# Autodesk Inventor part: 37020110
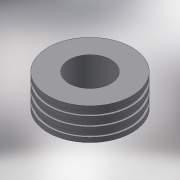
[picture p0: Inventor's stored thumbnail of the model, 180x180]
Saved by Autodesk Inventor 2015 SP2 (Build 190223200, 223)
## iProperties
Created: 2017-08
Part Number: 37020110
Material: Generic
Description: PLASSON MAN HOLE ADAPTOR 110
Document SubType Name: Modeling
Designer: Кирилл
Density: 1 g/cm^3
Appearance: Default
Author: Кирилл
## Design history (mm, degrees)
derived "37020-477207.ipt"
feature "Solid1::37020-477207.ipt"
tag "TaggingFeature1"
body "Solid1"
other parameters: "d0" = 135, "d1" = 216, "d2" = 205.2, "d3" = 97, "d6" = 37, "L_" = 135, "d_1" = 97, "D_" = 216, "H_" = 37
